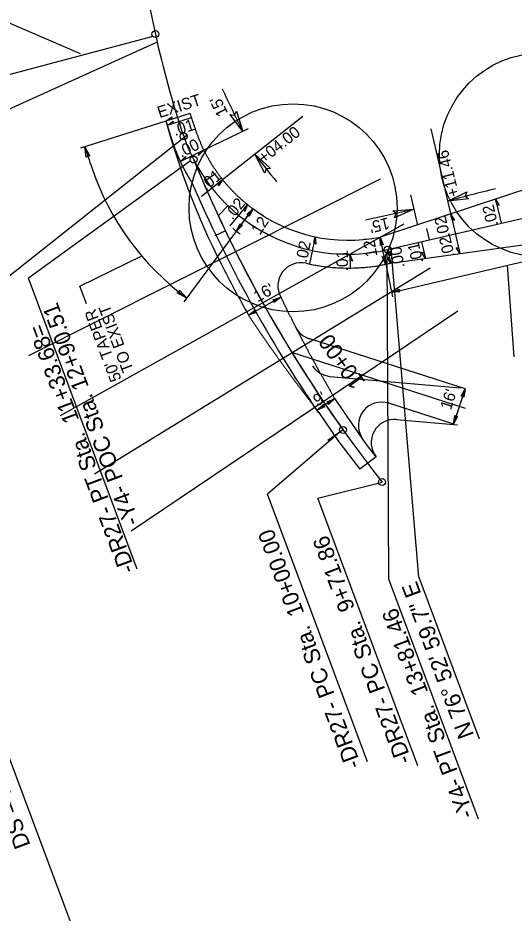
# Model space of a CAD drawing. Extents: x 472216 to 481979, y 489069 to 507339.
# Drawn here: x 478136.4 to 478350.7, y 494688.2 to 495074.7 of the extents above; entities that cross this region are included whole.
import ezdxf

# ---------------------------------------------------------------- set-up
doc = ezdxf.new("R2010")
doc.units = 0
for name, color, linetype in [('Default', 7, 'Continuous'), ('Exist Horizontal Alignment Point', 7, 'Continuous'), ('Old_Level_12', 7, 'Continuous'), ('Prop Drainage Structure Drop Inlet Grate 2 Narrow Slots and Sag Grates 840 24 CELL', 7, 'Continuous'), ('Prop Drainage Structure Drop Inlet Grate 2 Wide Slots and Sag Grates 840 22 Label', 7, 'Continuous'), ('Prop Drainage Structure Outlet Berm Ditch 850 10 CELL', 7, 'Continuous'), ('Prop Drainage Structure Pipe CSP 15in', 7, 'Continuous'), ('Prop Drainage Structure Pipe RCP 24in Class III', 7, 'Continuous'), ('Prop Drainage Structure Pipe RCP 24in Class III Label', 7, 'Continuous'), ('Prop Rem of Exist Asph Pvmt', 7, 'Continuous'), ('Sheet Block Revision CELL', 7, 'Continuous'), ('Sheet Clip Boundary CELL', 7, 'Continuous'), ('Sheet North Arrow Point CELL', 7, 'Continuous'), ('Sheet PE Seal Cell', 7, 'Continuous'), ('Sheet Plan And Profile CELL', 7, 'Continuous'), ('Sheet Plot Border Inside CELL', 7, 'Continuous'), ('Sheet Plot Border Outside CELL', 7, 'Continuous'), ('Sheet Profile Grid Major CELL', 7, 'Continuous'), ('Sheet Profile Grid Minor CELL', 7, 'Continuous')]:
    doc.layers.add(name, color=color, linetype=linetype)

msp = doc.modelspace()

# ---------------------------------------------------------------- linework, layer by layer
at = {"layer": 'Default'}
msp.add_line((478291.08, 494885.25), (478284.06, 494879.89), dxfattribs=at)
at = {"layer": 'Exist Horizontal Alignment Point'}
msp.add_lwpolyline([(478280.96, 494044.15), (477922.14, 495005.46), (478024.87, 495043.81), (478383.69, 494082.49)], close=True, dxfattribs=at)
at = {"layer": 'Old_Level_12'}
for p, q in [((478194.7, 495066.65), (478125.51, 495048.31)), ((478196.55, 495064.17), (478111.41, 495025.8)), ((478209.43, 495024.08), (478109.07, 494944.54)), ((478210.85, 495013.01), (478140.94, 494962.37)), ((478295.73, 494973.2), (478296.44, 494832.5)), ((478187.83, 494836.77), (478140.94, 494962.37)), ((478275.56, 494895.97), (478244.19, 494869.04)), ((478265.92, 494867.33), (478293.64, 494874.31)), ((478287.32, 494753.49), (478244.19, 494869.04)), ((478309.05, 494751.78), (478265.92, 494867.33)), ((478309.47, 494833.21), (478335.53, 494763.41)), ((478296.44, 494832.5), (478335.09, 494728.95))]:
    msp.add_line(p, q, dxfattribs=at)
for centre in [(478195.76, 495067.71), (478195.76, 495067.71), (478208.01, 495023.59), (478212.24, 495013.59), (478212.24, 495013.59), (478296.05, 494974.67), (478276.78, 494896.84), (478293.64, 494874.31)]:
    msp.add_circle(centre, 1.5, dxfattribs=at)
at = {"layer": 'Prop Drainage Structure Drop Inlet Grate 2 Narrow Slots and Sag Grates 840 24 CELL'}
for points in [[(478200.31, 495030.17), (478202.87, 495032.03), (478202.52, 495030.87)], [(478200.9, 495028.23), (478203.45, 495030.1), (478203.1, 495028.94)], [(478206.54, 495012.66), (478208.81, 495014.87), (478208.62, 495013.67)], [(478216.68, 495017.57), (478214.42, 495015.36), (478214.6, 495016.56)], [(478224.81, 495004.82), (478223.07, 495002.17), (478222.99, 495003.38)], [(478342.62, 494996.42), (478344.27, 494993.72), (478343.14, 494994.17)], [(478235.49, 494994.15), (478234.37, 494991.2), (478234.03, 494992.36)], [(478323.28, 494990), (478324.94, 494987.31), (478323.81, 494987.75)], [(478264.72, 494980.21), (478265.08, 494977.07), (478264.24, 494977.95)], [(478327.25, 494972.95), (478325.6, 494975.65), (478326.73, 494975.21)], [(478279.78, 494972.72), (478280.81, 494969.73), (478279.81, 494970.4)], [(478296.05, 494974.67), (478297.7, 494971.97), (478296.57, 494972.42)], [(478312.33, 494970.89), (478310.68, 494973.59), (478311.81, 494973.14)], [(478297.45, 494968.66), (478295.79, 494971.36), (478296.92, 494970.92)]]:
    msp.add_lwpolyline(points, close=True, dxfattribs=at)
at = {"layer": 'Prop Drainage Structure Drop Inlet Grate 2 Wide Slots and Sag Grates 840 22 Label'}
for p, q in [((478210.69, 495033.46), (478200.31, 495030.17)), ((478211.27, 495031.56), (478200.9, 495028.23)), ((478259.42, 495032.2), (478224.81, 495004.82)), ((478235.76, 495026.79), (478216.68, 495017.57)), ((478314.71, 495026.75), (478323.2, 494990.32)), ((478216.68, 495017.57), (478206.54, 495012.66)), ((478224.81, 495004.82), (478215.71, 494997.62)), ((478305.94, 494998.31), (478308.98, 494985.26)), ((478342.62, 494996.42), (478345.03, 494986.08)), ((478235.49, 494994.15), (478227.96, 494984.9)), ((478323.28, 494990), (478327.25, 494972.95)), ((478264.72, 494980.21), (478262.25, 494968.54)), ((478310.66, 494978.07), (478312.33, 494970.89)), ((478279.78, 494972.72), (478279.84, 494966.78)), ((478296.05, 494974.67), (478297.45, 494968.66))]:
    msp.add_line(p, q, dxfattribs=at)
for points in [[(478230.83, 495034.41), (478233.49, 495025.68), (478228, 495033.04), (478229.94, 495032.73)], [(478242.99, 495007.75), (478238.71, 495015.82), (478245.51, 495009.64), (478243.54, 495009.57)], [(478331.05, 494996.59), (478321.97, 494995.59), (478330.23, 494999.63), (478329.56, 494997.78)], [(478298.26, 494991.48), (478307.36, 494992.19), (478298.98, 494988.42), (478299.7, 494990.25)]]:
    msp.add_lwpolyline(points, close=True, dxfattribs=at)
for centre, start, end in [((479048.35, 495430.76), 205.14765, 206.43155), ((478957.01, 495574.51), 217.87575, 218.82019), ((478560.24, 494117.34), 103.83329, 105.17894), ((478097.65, 495877.69), 281.97813, 283.32378)]:
    msp.add_arc(centre, 910, start, end, dxfattribs=at)
at = {"layer": 'Prop Drainage Structure Outlet Berm Ditch 850 10 CELL'}
for points in [[(478165.92, 495014.58), (478165.29, 495019.1), (478167.43, 495015.04), (478166.49, 495015.34)], [(478235.24, 494989.8), (478237.89, 494992.32), (478236.24, 494989.03), (478236, 494989.78)], [(478233.38, 494985.2), (478230.73, 494982.68), (478232.38, 494985.97), (478232.62, 494985.22)], [(478292.92, 494976.45), (478292.81, 494980.1), (478294.16, 494976.68), (478293.44, 494977.01)], [(478294.98, 494971.99), (478295.19, 494968.34), (478293.75, 494971.72), (478294.47, 494971.42)], [(478206.23, 494957.19), (478209.27, 494953.78), (478205.23, 494955.98), (478206.18, 494956.24)], [(478301.33, 494956.43), (478297.68, 494956.21), (478301.06, 494957.66), (478300.76, 494956.93)], [(478246.49, 494952.93), (478249.94, 494954.13), (478247.09, 494951.82), (478247.18, 494952.6)], [(478239.39, 494947.58), (478235.94, 494946.38), (478238.8, 494948.69), (478238.71, 494947.91)], [(478327.77, 494911.4), (478329.47, 494914.63), (478328.96, 494910.99), (478328.5, 494911.63)], [(478269.88, 494908.9), (478273.2, 494910.43), (478270.58, 494907.85), (478270.59, 494908.64)], [(478268.98, 494906.86), (478265.64, 494905.38), (478268.29, 494907.92), (478268.27, 494907.13)], [(478326.22, 494902.65), (478324.52, 494899.42), (478325.03, 494903.06), (478325.5, 494902.42)]]:
    msp.add_lwpolyline(points, close=True, dxfattribs=at)
at = {"layer": 'Prop Drainage Structure Pipe RCP 24in Class III'}
msp.add_line((478222.92, 494989.29), (478227.08, 494993.62), dxfattribs=at)
msp.add_arc((478757.55, 495238.84), 590, 202.43955, 215.42657, dxfattribs=at)
at = {"layer": 'Prop Drainage Structure Pipe RCP 24in Class III Label'}
for p, q in [((478388.2, 495011.54), (478292.81, 494980.1)), ((478395.01, 494982.33), (478295.31, 494968.37)), ((478329.46, 494914.58), (478262.07, 494936.24)), ((478324.56, 494899.35), (478329.46, 494914.58)), ((478273.91, 494909.4), (478273.2, 494910.43)), ((478324.56, 494899.35), (478296.49, 494908.37)), ((478266.39, 494904.28), (478265.64, 494905.38)), ((478291.08, 494885.25), (478284.06, 494879.89))]:
    msp.add_line(p, q, dxfattribs=at)
for points in [[(478291.08, 494885.25), (478286.95, 494890.54), (478273.91, 494909.4)], [(478266.39, 494904.28), (478274.57, 494892.33), (478284.06, 494879.89)]]:
    msp.add_lwpolyline(points, dxfattribs=at)
for centre, radius, start, end in [((478518.5, 495117.68), 330, 195.3773, 206.8776), ((478279.03, 495047.71), 69, 233.3182, 281.5233), ((478757.55, 495238.84), 598, 206.87764, 209.27898), ((478258.66, 494959.02), 10, 77.0704, 209.2879), ((478279.03, 495047.71), 81, 257.0704, 281.5233), ((478265.25, 494945.72), 10, 207.0222, 252.1873), ((478293.43, 494898.85), 10, 72.1873, 213.4846)]:
    msp.add_arc(centre, radius, start, end, dxfattribs=at)
for points in [[(478210.66, 495033.55), (478210.87, 495032.91), (478211.08, 495032.28), (478211.29, 495031.64), (478211.5, 495031.01), (478211.71, 495030.38), (478211.92, 495029.74), (478212.13, 495029.11), (478212.35, 495028.48), (478212.56, 495027.84), (478212.78, 495027.21), (478213, 495026.58), (478213.21, 495025.95), (478213.43, 495025.32), (478213.66, 495024.67), (478213.9, 495024.03), (478214.14, 495023.39), (478214.39, 495022.75), (478214.64, 495022.12), (478214.9, 495021.49), (478215.17, 495020.86), (478215.44, 495020.23), (478215.72, 495019.61), (478216, 495018.99), (478216.29, 495018.37), (478216.59, 495017.75), (478216.89, 495017.14), (478217.2, 495016.53), (478217.52, 495015.93), (478217.84, 495015.33), (478218.17, 495014.73), (478218.5, 495014.13), (478218.84, 495013.54), (478219.18, 495012.95), (478219.53, 495012.36), (478219.89, 495011.78), (478220.25, 495011.2), (478220.62, 495010.63), (478220.99, 495010.05), (478221.37, 495009.49), (478221.75, 495008.92), (478222.14, 495008.36), (478222.54, 495007.81), (478222.94, 495007.25), (478223.34, 495006.71), (478223.75, 495006.16), (478224.17, 495005.62), (478224.59, 495005.09), (478225.02, 495004.56), (478225.45, 495004.03), (478225.89, 495003.51), (478226.33, 495002.99), (478226.78, 495002.47), (478227.23, 495001.96), (478227.69, 495001.46), (478228.15, 495000.96), (478228.62, 495000.46), (478229.09, 494999.97), (478229.57, 494999.48), (478230.05, 494999), (478230.53, 494998.52), (478231.03, 494998.05), (478231.52, 494997.59), (478232.02, 494997.12), (478232.53, 494996.67), (478233.03, 494996.21), (478233.55, 494995.77), (478234.07, 494995.32), (478234.59, 494994.89), (478235.11, 494994.46), (478235.64, 494994.03), (478236.18, 494993.61), (478236.72, 494993.19), (478237.81, 494992.38)], [(478249.92, 494954.17), (478250.21, 494953.57), (478250.5, 494952.96), (478250.79, 494952.36), (478251.08, 494951.76), (478251.37, 494951.16), (478251.66, 494950.56), (478251.96, 494949.96), (478252.25, 494949.36), (478252.55, 494948.76), (478252.84, 494948.16), (478253.14, 494947.56), (478253.43, 494946.96), (478253.73, 494946.36), (478254.03, 494945.76), (478254.33, 494945.17), (478254.63, 494944.57), (478254.93, 494943.97), (478255.23, 494943.37), (478255.53, 494942.78), (478255.83, 494942.18), (478256.14, 494941.58), (478256.44, 494940.99), (478256.74, 494940.39), (478257.05, 494939.8), (478257.36, 494939.2), (478257.66, 494938.61), (478257.97, 494938.01), (478258.28, 494937.42), (478258.59, 494936.82), (478258.9, 494936.23), (478259.21, 494935.64), (478259.52, 494935.04), (478259.83, 494934.45), (478260.14, 494933.86), (478260.45, 494933.27), (478260.77, 494932.68), (478261.08, 494932.08), (478261.4, 494931.49), (478261.71, 494930.9), (478262.03, 494930.31), (478262.35, 494929.72), (478262.66, 494929.13), (478262.98, 494928.54), (478263.3, 494927.95), (478263.62, 494927.37), (478263.94, 494926.78), (478264.26, 494926.19), (478264.59, 494925.6), (478264.91, 494925.01), (478265.23, 494924.43), (478265.56, 494923.84), (478265.88, 494923.25), (478266.21, 494922.67), (478266.53, 494922.08), (478266.86, 494921.5), (478267.19, 494920.91), (478267.52, 494920.33), (478267.85, 494919.74), (478268.18, 494919.16), (478268.51, 494918.57), (478268.84, 494917.99), (478269.17, 494917.41), (478269.5, 494916.82), (478269.83, 494916.24), (478270.17, 494915.66), (478270.5, 494915.08), (478270.84, 494914.5), (478271.17, 494913.92), (478271.51, 494913.34), (478271.85, 494912.75), (478272.19, 494912.17), (478272.53, 494911.6), (478273.21, 494910.44)], [(478235.96, 494946.34), (478236.34, 494945.77), (478236.72, 494945.2), (478237.1, 494944.63), (478237.49, 494944.06), (478237.87, 494943.48), (478238.25, 494942.91), (478238.63, 494942.35), (478239.02, 494941.78), (478239.4, 494941.21), (478239.78, 494940.64), (478240.17, 494940.07), (478240.56, 494939.5), (478240.94, 494938.94), (478241.33, 494938.37), (478241.72, 494937.81), (478242.11, 494937.24), (478242.5, 494936.68), (478242.89, 494936.11), (478243.28, 494935.55), (478243.67, 494934.99), (478244.06, 494934.42), (478244.45, 494933.86), (478244.84, 494933.3), (478245.24, 494932.74), (478245.63, 494932.18), (478246.03, 494931.62), (478246.42, 494931.06), (478246.82, 494930.5), (478247.21, 494929.94), (478247.61, 494929.38), (478248.01, 494928.82), (478248.41, 494928.27), (478248.8, 494927.71), (478249.2, 494927.15), (478249.6, 494926.6), (478250.01, 494926.04), (478250.41, 494925.49), (478250.81, 494924.93), (478251.21, 494924.38), (478251.61, 494923.83), (478252.02, 494923.28), (478252.42, 494922.72), (478252.83, 494922.17), (478253.23, 494921.62), (478253.64, 494921.07), (478254.05, 494920.52), (478254.45, 494919.97), (478254.86, 494919.42), (478255.27, 494918.87), (478255.68, 494918.33), (478256.09, 494917.78), (478256.5, 494917.23), (478256.91, 494916.68), (478257.32, 494916.14), (478257.73, 494915.59), (478258.15, 494915.05), (478258.56, 494914.5), (478258.97, 494913.96), (478259.39, 494913.42), (478259.8, 494912.87), (478260.22, 494912.33), (478260.64, 494911.79), (478261.05, 494911.25), (478261.47, 494910.71), (478261.89, 494910.17), (478262.31, 494909.63), (478262.73, 494909.09), (478263.15, 494908.55), (478263.57, 494908.01), (478263.99, 494907.48), (478264.41, 494906.94), (478264.83, 494906.4), (478265.68, 494905.33)]]:
    msp.add_spline(points, degree=3, dxfattribs=at)
at = {"layer": 'Sheet Block Revision CELL'}
for p, q in [((478127.47, 495074.71), (478163.24, 495059.29)), ((478200.31, 495030.17), (478163.38, 495018.5)), ((478237.89, 494992.32), (478208.07, 494952.18)), ((478230.73, 494982.68), (478237.89, 494992.32)), ((478295.21, 494968.35), (478292.81, 494980.1)), ((478297.68, 494956.21), (478395.76, 494979.07)), ((478163.2, 494958.92), (478189.9, 494971.92)), ((478295.21, 494968.35), (478298.08, 494954.25)), ((478350.65, 494928.32), (478347.79, 494967.89)), ((478166.04, 494951.31), (478163.2, 494958.92)), ((478249.94, 494954.13), (478235.94, 494946.38)), ((478329.47, 494914.63), (478324.52, 494899.42)), ((478273.21, 494910.44), (478265.64, 494905.38))]:
    msp.add_line(p, q, dxfattribs=at)
for centre, radius, start, end in [((478591.5, 495153.84), 447, 197.543, 198.7591), ((478279.03, 495047.71), 117, 198.7591, 233.3997), ((478279.03, 495047.71), 81, 231.9848, 234.8145)]:
    msp.add_arc(centre, radius, start, end, dxfattribs=at)
at = {"layer": 'Sheet Clip Boundary CELL'}
msp.add_line((478329.7, 494906.1), (478254.72, 494930.2), dxfattribs=at)
msp.add_arc((478279.03, 495047.71), 81, 257.0704, 283.1168, dxfattribs=at)
at = {"layer": 'Sheet North Arrow Point CELL'}
for p, q in [((478169.19, 495189.81), (478195.76, 495067.71)), ((478296.05, 494974.67), (478457.03, 495012.18))]:
    msp.add_line(p, q, dxfattribs=at)
for centre, radius, start, end in [((481983.35, 496141.85), 3720, 188.99254, 203.7418), ((478591.5, 495153.84), 405, 192.2783, 198.7591), ((478279.03, 495047.71), 75, 198.7591, 283.1168), ((478757.55, 495238.84), 590, 202.44434, 218.15974)]:
    msp.add_arc(centre, radius, start, end, dxfattribs=at)
at = {"layer": 'Sheet PE Seal Cell'}
for p, q in [((478217.59, 495004.69), (478221.69, 495007.56)), ((478314.11, 494978.88), (478312.97, 494983.75)), ((478225.98, 494982.84), (478221.48, 494980.67)), ((478225.98, 494982.84), (478221.48, 494980.67))]:
    msp.add_line(p, q, dxfattribs=at)
at = {"layer": 'Sheet Plan And Profile CELL'}
msp.add_line((478309.47, 494833.21), (478297.51, 494975.01), dxfattribs=at)
at = {"layer": 'Sheet Plot Border Inside CELL'}
for p, q in [((478141.05, 494928.96), (478292.94, 495005.3)), ((478154.73, 494903.12), (478303.25, 494985.83)), ((478169.49, 494877.88), (478314.37, 494966.82)), ((478185.31, 494853.3), (478326.3, 494948.29)), ((478271.11, 494919.95), (478327.54, 494914.99)), ((478299.84, 494901.37), (478326.14, 494899.05))]:
    msp.add_line(p, q, dxfattribs=at)
for centre, radius, start, end in [((478757.55, 495238.84), 594.5, 203.33786, 214.26123), ((478271.99, 494929.92), 10, 212.4656, 264.9732), ((478298.97, 494891.4), 10, 84.9732, 217.9632)]:
    msp.add_arc(centre, radius, start, end, dxfattribs=at)
msp.add_open_spline([(478200.28, 495030.27), (478200.35, 495030.05), (478200.42, 495029.83), (478200.48, 495029.61), (478200.55, 495029.39), (478200.61, 495029.17), (478200.68, 495028.95), (478200.75, 495028.74), (478200.81, 495028.52), (478200.88, 495028.3), (478200.95, 495028.08), (478201.01, 495027.86), (478201.08, 495027.64), (478201.15, 495027.42), (478201.22, 495027.2), (478201.28, 495026.99), (478201.35, 495026.77), (478201.42, 495026.55), (478201.49, 495026.33), (478201.55, 495026.11), (478201.62, 495025.89), (478201.69, 495025.68), (478201.76, 495025.46), (478201.83, 495025.24), (478201.9, 495025.02), (478201.97, 495024.8), (478202.03, 495024.58), (478202.1, 495024.37), (478202.17, 495024.15), (478202.24, 495023.93), (478202.31, 495023.71), (478202.38, 495023.49), (478202.45, 495023.28), (478202.52, 495023.06), (478202.59, 495022.84), (478202.66, 495022.62), (478202.73, 495022.4), (478202.8, 495022.18), (478202.87, 495021.96), (478202.95, 495021.73), (478203.03, 495021.48), (478203.11, 495021.23), (478203.2, 495020.98), (478203.28, 495020.73), (478203.37, 495020.48), (478203.45, 495020.23), (478203.54, 495019.98), (478203.63, 495019.73), (478203.72, 495019.48), (478203.81, 495019.24), (478203.9, 495018.99), (478203.99, 495018.74), (478204.08, 495018.49), (478204.18, 495018.24), (478204.27, 495018), (478204.37, 495017.75), (478204.46, 495017.5), (478204.56, 495017.26), (478204.66, 495017.01), (478204.76, 495016.77), (478204.85, 495016.52), (478204.95, 495016.28), (478205.06, 495016.03), (478205.16, 495015.79), (478205.26, 495015.54), (478205.36, 495015.3), (478205.47, 495015.06), (478205.57, 495014.81), (478205.68, 495014.57), (478205.78, 495014.33), (478205.89, 495014.09), (478206, 495013.85), (478206.11, 495013.6), (478206.22, 495013.36), (478206.33, 495013.12), (478206.44, 495012.88), (478206.55, 495012.64), (478206.66, 495012.4), (478206.78, 495012.16), (478206.89, 495011.92), (478207, 495011.69), (478207.12, 495011.45), (478207.24, 495011.21), (478207.35, 495010.97), (478207.47, 495010.74), (478207.59, 495010.5), (478207.71, 495010.26), (478207.83, 495010.03), (478207.95, 495009.79), (478208.08, 495009.56), (478208.2, 495009.32), (478208.32, 495009.09), (478208.45, 495008.86), (478208.57, 495008.62), (478208.7, 495008.39), (478208.82, 495008.16), (478208.95, 495007.92), (478209.08, 495007.69), (478209.21, 495007.46), (478209.34, 495007.23), (478209.47, 495007), (478209.6, 495006.77), (478209.73, 495006.54), (478209.87, 495006.31), (478210, 495006.08), (478210.13, 495005.85), (478210.27, 495005.63), (478210.4, 495005.4), (478210.54, 495005.17), (478210.68, 495004.94), (478210.82, 495004.72), (478210.96, 495004.49), (478211.1, 495004.27), (478211.24, 495004.04), (478211.38, 495003.82), (478211.48, 495003.66), (478211.58, 495003.5), (478211.68, 495003.34)], degree=3, dxfattribs=at)
at = {"layer": 'Sheet Plot Border Outside CELL'}
for centre, radius in [((478362.44, 495015.53), 44.04), ((478255.2, 494992.72), 44.91)]:
    msp.add_circle(centre, radius, dxfattribs=at)
at = {"layer": 'Sheet Profile Grid Minor CELL'}
msp.add_line((478276.78, 494896.84), (478270.26, 494892.2), dxfattribs=at)
msp.add_line((478276.78, 494896.84), (478270.26, 494892.2), dxfattribs=at)

# ---------------------------------------------------------------- texts
at = {"layer": 'Old_Level_12'}
for s, p in [('-Y4- POC Sta. 12+90.51', (478188.95, 494856.99)), ('-DR27- PT Sta.  11+33.68=', (478187.17, 494836.39)), ('-DR27- PC Sta.  10+00.00', (478284.7, 494752.04)), ('-DR27- PC Sta.  9+71.86', (478306.55, 494754.07)), ('-Y4- PT Sta.  13+81.46', (478333.49, 494730.54))]:
    msp.add_text(s, height=7, rotation=110.469, dxfattribs=at).set_placement(p)
at = {"layer": 'Prop Drainage Structure Drop Inlet Grate 2 Wide Slots and Sag Grates 840 22 Label'}
for s, rotation, p in [('EXIST', 17.543, (478197.53, 495031.43)), ("15'", 116.1856, (478227.23, 495033.64)), ('.01', 17.543, (478204.23, 495023.68)), ('+04.00', 38.348, (478242.63, 495011.63)), ('.00', 25.8049, (478206.89, 495014.27)), ('+11.46', 104.199, (478327.08, 494998.08)), ('.01', 38.7929, (478217.58, 494999.9)), ('.02', 51.336, (478229.05, 494987.22)), ('.02', 103.1168, (478343.79, 494985.42)), ("15'", 193.7384, (478296.16, 494988.63)), ('.02', 103.1168, (478323.09, 494980.44)), ('.02', 103.1168, (478325.1, 494971.87)), ('.02', 78.4793, (478261.08, 494968.81)), ('.00', 99.7366, (478303.4, 494967.14)), ('.01', 103.5564, (478311.53, 494969.27)), ('.01', 91.0161, (478279, 494965.33))]:
    msp.add_text(s, height=5, rotation=rotation, dxfattribs=at).set_placement(p)
at = {"layer": 'Prop Drainage Structure Pipe CSP 15in'}
for s, rotation, p in [("12'", 56.335, (478240.86, 494980.67)), ("12'", 100.2433, (478291.65, 494971.92)), ("16'", 28.9554, (478239.89, 494951.82)), ("50' TAPER ", 110.469, (478181.2, 494918.72)), ('TO EXIST', 110.469, (478186.44, 494922.82)), ("16'", 71.9543, (478323.32, 494905.12)), ("9'", 28.9554, (478265.62, 494906.92))]:
    msp.add_text(s, height=5, rotation=rotation, dxfattribs=at).set_placement(p)
at = {"layer": 'Prop Rem of Exist Asph Pvmt'}
msp.add_text('DS = 15 MPH', height=7, rotation=110.469, dxfattribs=at).set_placement((478141.9, 494717.57))
at = {"layer": 'Sheet Plan And Profile CELL'}
msp.add_text('N 76%%d 52\' 59.7" E', height=7, rotation=110.469, dxfattribs=at).set_placement((478333.43, 494765.11))
at = {"layer": 'Sheet Profile Grid Major CELL'}
msp.add_text('10+00', height=7, rotation=125.4266, dxfattribs=at).set_placement((478286.65, 494917.56))

doc.saveas('drawing.dxf')
